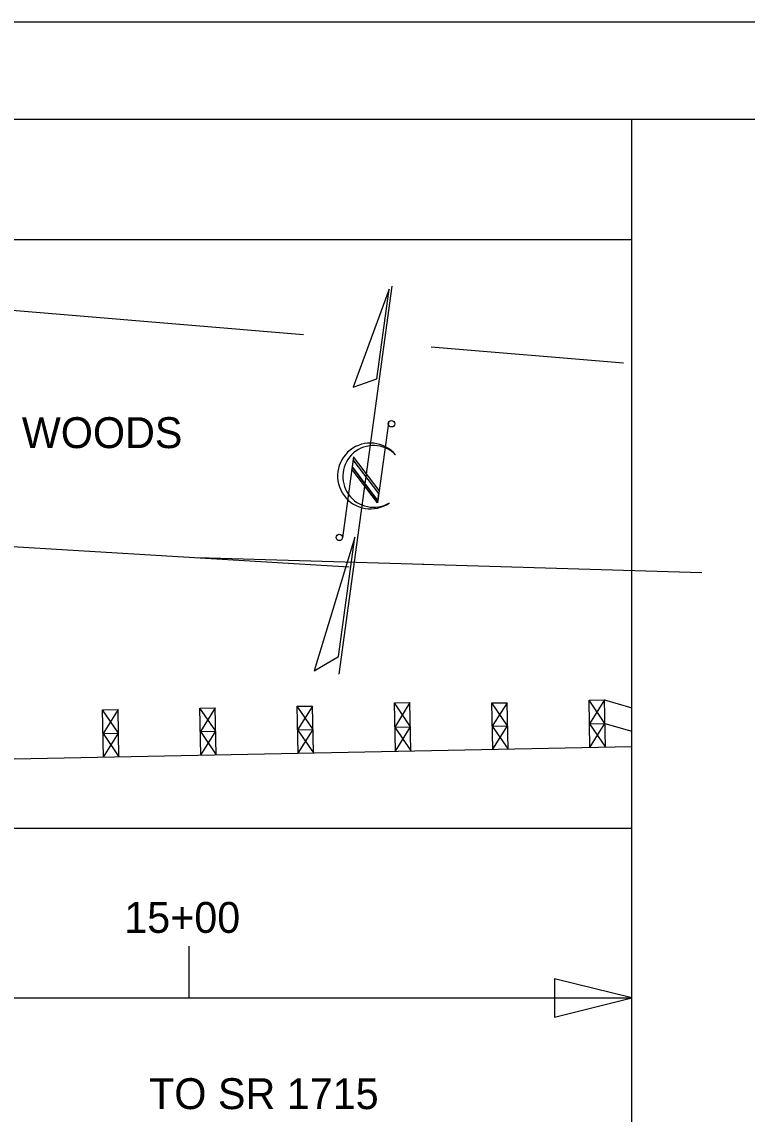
# Model space of a CAD drawing. Extents: x 471 to 2034, y -623 to 126.
# Drawn here: x 765.8 to 812.8, y -294.1 to -223.4 of the extents above; entities that cross this region are included whole.
import ezdxf

# ---------------------------------------------------------------- set-up
doc = ezdxf.new("R2010")
doc.units = 0
for name, color, linetype in [('Arrowhead Terminators CELL', 7, 'Continuous'), ('Default', 7, 'Continuous'), ('Exist Vegetation Woods Line', 7, 'Continuous'), ('Plan Sheet CELL', 7, 'Continuous'), ('Plot Shape CELL', 7, 'Continuous'), ('Prop EOT', 7, 'Continuous'), ('Prop Horizontal Alignment', 7, 'Continuous'), ('Prop Horizontal Alignment Tick Large', 7, 'Continuous'), ('Sheet North Arrow CELL', 7, 'Continuous'), ('Text', 7, 'Continuous')]:
    doc.layers.add(name, color=color, linetype=linetype)

msp = doc.modelspace()

# ---------------------------------------------------------------- linework, layer by layer
at = {"layer": 'Arrowhead Terminators CELL'}
msp.add_lwpolyline([(805.312, -286.575), (800.312, -285.325), (800.312, -287.825)], close=True, dxfattribs=at)
at = {"layer": 'Default'}
for p, q in [((802.544, -267.289), (803.544, -267.269)), ((803.544, -267.269), (802.575, -268.82)), ((803.605, -270.332), (803.544, -267.269)), ((803.544, -267.269), (805.312, -267.794)), ((771.044, -267.93), (772.044, -267.91)), ((771.105, -270.982), (771.044, -267.93)), ((772.075, -269.436), (771.044, -267.93)), ((772.044, -267.91), (771.075, -269.456)), ((772.105, -270.962), (772.044, -267.91)), ((777.344, -267.809), (778.344, -267.789)), ((777.405, -270.856), (777.344, -267.809)), ((778.375, -269.312), (777.344, -267.809)), ((778.344, -267.789), (777.375, -269.332)), ((778.405, -270.836), (778.344, -267.789)), ((783.644, -267.695), (784.644, -267.675)), ((783.705, -270.73), (783.644, -267.695)), ((784.675, -269.192), (783.644, -267.695)), ((784.644, -267.675), (783.675, -269.212)), ((784.705, -270.71), (784.644, -267.675)), ((789.942, -267.467), (790.942, -267.447)), ((790.005, -270.604), (789.942, -267.467)), ((790.973, -269.016), (789.942, -267.467)), ((790.942, -267.447), (789.973, -269.036)), ((791.005, -270.584), (790.942, -267.447)), ((796.245, -267.479), (797.245, -267.459)), ((796.305, -270.478), (796.245, -267.479)), ((797.275, -268.958), (796.245, -267.479)), ((797.245, -267.459), (796.275, -268.978)), ((797.305, -270.458), (797.245, -267.459)), ((802.605, -270.352), (802.544, -267.289)), ((803.575, -268.8), (802.544, -267.289)), ((777.375, -269.332), (778.375, -269.312)), ((777.375, -269.332), (778.405, -270.836)), ((777.405, -270.856), (778.375, -269.312)), ((783.675, -269.212), (784.675, -269.192)), ((783.675, -269.212), (784.705, -270.71)), ((783.705, -270.73), (784.675, -269.192)), ((789.973, -269.036), (790.973, -269.016)), ((789.973, -269.036), (791.005, -270.584)), ((790.005, -270.604), (790.973, -269.016)), ((796.275, -268.978), (797.275, -268.958)), ((796.275, -268.978), (797.305, -270.458)), ((796.305, -270.478), (797.275, -268.958)), ((802.575, -268.82), (803.575, -268.8)), ((802.575, -268.82), (803.605, -270.332)), ((802.605, -270.352), (803.575, -268.8)), ((803.575, -268.8), (805.312, -269.305)), ((771.075, -269.456), (772.075, -269.436)), ((771.075, -269.456), (772.105, -270.962)), ((771.105, -270.982), (772.075, -269.436)), ((762.263, -271.159), (805.312, -270.298)), ((783.705, -270.73), (784.705, -270.71))]:
    msp.add_line(p, q, dxfattribs=at)
at = {"layer": 'Exist Vegetation Woods Line'}
for points in [[(787.016, -258.677), (735.516, -255.58), (707.382, -253.971), (676.992, -240.962), (672.242, -237.475)], [(752.781, -241.006), (784.051, -243.632)], [(792.318, -244.42), (804.779, -245.466)], [(791.846, -258.523), (777.22, -258.088)], [(809.853, -259.059), (791.769, -258.521)]]:
    msp.add_lwpolyline(points, dxfattribs=at)
at = {"layer": 'Plan Sheet CELL'}
for p, q in [((564.339, -229.69), (1076.344, -229.69)), ((564.339, -237.475), (805.312, -237.475))]:
    msp.add_line(p, q, dxfattribs=at)
msp.add_lwpolyline([(564.339, -339.883), (805.312, -339.883), (805.312, -229.69)], dxfattribs=at)
at = {"layer": 'Plot Shape CELL'}
msp.add_lwpolyline([(547.474, -223.388), (1076.484, -223.388), (1076.484, -575.388), (547.474, -575.388)], close=True, dxfattribs=at)
at = {"layer": 'Prop EOT'}
msp.add_line((564.339, -275.575), (805.312, -275.575), dxfattribs=at)
at = {"layer": 'Prop Horizontal Alignment'}
msp.add_line((637.709, -286.575), (805.312, -286.575), dxfattribs=at)
msp.add_line((637.709, -286.575), (805.312, -286.575), dxfattribs=at)
at = {"layer": 'Prop Horizontal Alignment Tick Large'}
msp.add_line((776.644, -286.575), (776.644, -283.211), dxfattribs=at)
at = {"layer": 'Sheet North Arrow CELL'}
for p, q in [((786.366, -265.621), (789.796, -240.504)), ((789.549, -249.374), (788.845, -254.529)), ((787.297, -251.542), (786.581, -256.782)), ((788.955, -253.725), (787.297, -251.542)), ((789.998, -251.392), (790.022, -251.415)), ((788.845, -254.529), (787.187, -252.346)), ((787.271, -251.732), (787.207, -252.203)), ((788.865, -254.386), (787.207, -252.203)), ((787.207, -252.203), (788.865, -254.386)), ((788.929, -253.914), (787.271, -251.732)), ((788.865, -254.386), (788.929, -253.914))]:
    msp.add_line(p, q, dxfattribs=at)
for points in [[(789.592, -240.701), (787.268, -247.027), (788.801, -246.497)], [(787.37, -256.744), (784.739, -265.399), (786.314, -264.472)]]:
    msp.add_lwpolyline(points, close=True, dxfattribs=at)
for centre in [(789.754, -249.406), (786.375, -256.762)]:
    msp.add_circle(centre, 0.207, dxfattribs=at)
for centre, radius, start, end in [((788.391, -252.785), 2.129, 40.06351, 304.61755), ((788.595, -252.812), 1.996, 45.31853, 300.8522)]:
    msp.add_arc(centre, radius, start, end, dxfattribs=at)

# ---------------------------------------------------------------- texts
at = {"layer": 'Text'}
for s, p in [('WOODS', (765.815, -250.98)), ('15+00', (772.446, -282.36)), ('TO SR 1715', (774.056, -293.768))]:
    msp.add_text(s, height=2, dxfattribs=at).set_placement(p)

doc.saveas('drawing.dxf')
